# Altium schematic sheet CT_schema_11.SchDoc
size 274 x 160 mm
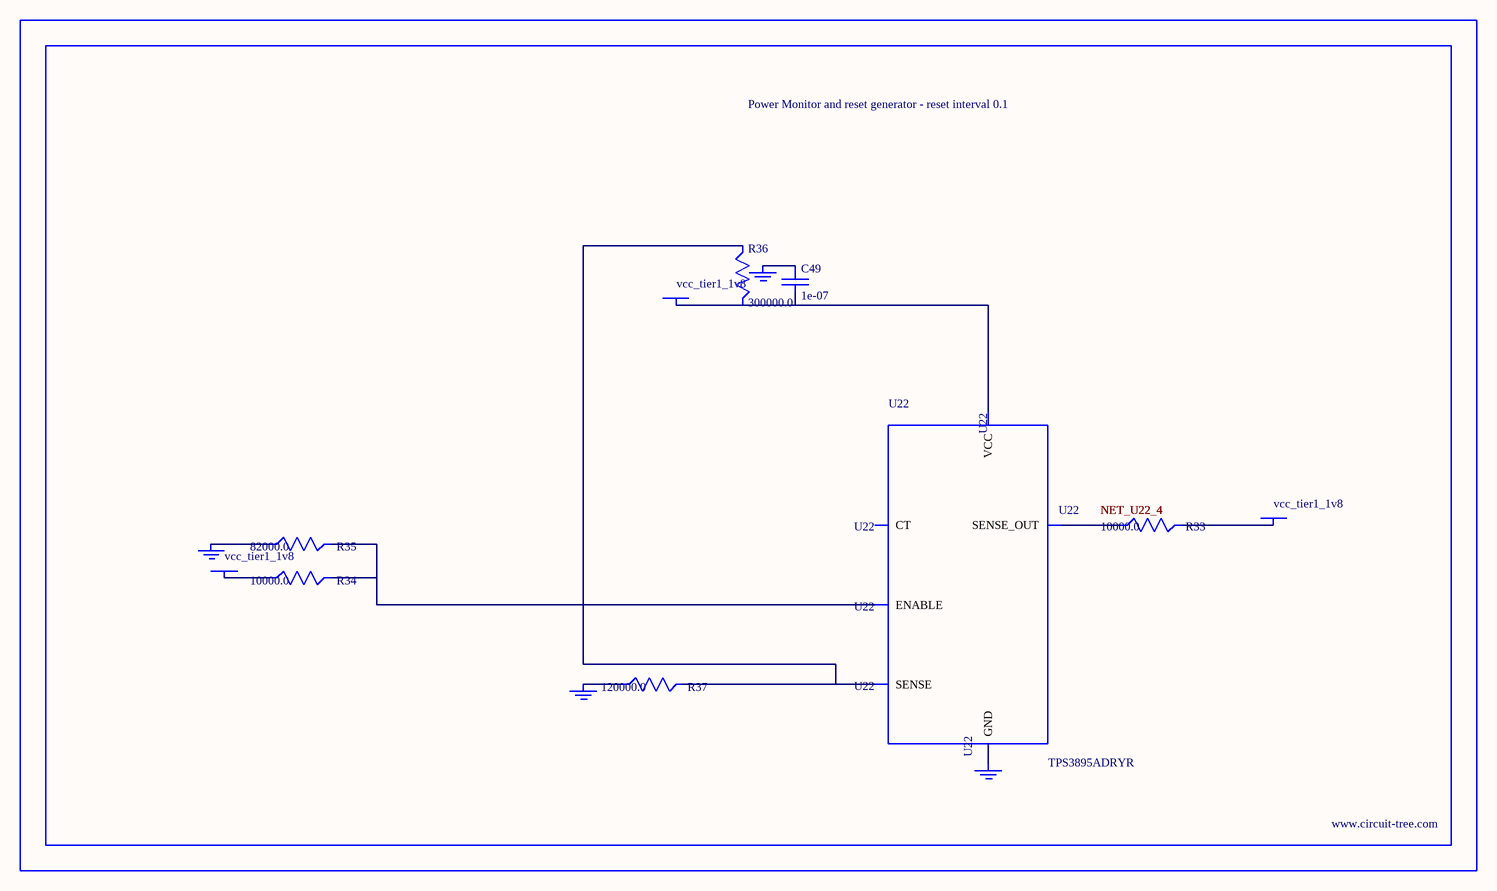
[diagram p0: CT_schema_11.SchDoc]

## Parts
BORDER10  (no value)
C49  1e-07  [C0402]
GND_INSTANCE_10_0  (no value)
GND_INSTANCE_10_1  (no value)
GND_INSTANCE_10_2  (no value)
GND_INSTANCE_10_3  (no value)
POWER_INSTANCE_10_0  vcc_tier1_1v8
POWER_INSTANCE_10_1  vcc_tier1_1v8
POWER_INSTANCE_10_2  vcc_tier1_1v8
R33  10000.0  [R0603]
R34  10000.0  [R0603]
R35  82000.0  [R0603]
R36  300000.0  [R0603]
R37  120000.0  [R0603]
U22  TPS3895ADRYR  [SON-6]

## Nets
NetC49_1: C49.1 GND_INSTANCE_10_2.0(GND)
NetC49_2: C49.2 POWER_INSTANCE_10_2.0(PWR) R36.2 U22.6(VCC)
NetGND_INSTANCE_10_0_0: GND_INSTANCE_10_0.0(GND) R35.1
NetGND_INSTANCE_10_1_0: GND_INSTANCE_10_1.0(GND) R37.1
NetGND_INSTANCE_10_3_0: GND_INSTANCE_10_3.0(GND) U22.2(GND)
NetPOWER_INSTANCE_10_0_0: POWER_INSTANCE_10_0.0(PWR) R34.1
NetPOWER_INSTANCE_10_1_0: POWER_INSTANCE_10_1.0(PWR) R33.2
NetR33_1: R33.1 U22.4(SENSE_OUT)
NetR34_2: R34.2 R35.2 U22.1(ENABLE)
NetR36_1: R36.1 R37.2 U22.3(SENSE)

Not connected (* = marked no-connect by the designer): U22 5(CT)

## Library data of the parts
BORDER10 = BORDER_PAGE10
C49 = C0402C104K3RACTU
GND_INSTANCE_10_0-GND_INSTANCE_10_3 = GND
POWER_INSTANCE_10_0-POWER_INSTANCE_10_2 = PWR
R33 R34 = RC0603JR-0710KL
R35 = RC0603JR-0782KL
R36 = RC0603JR-07300KL
R37 = RC0603JR-07120KL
